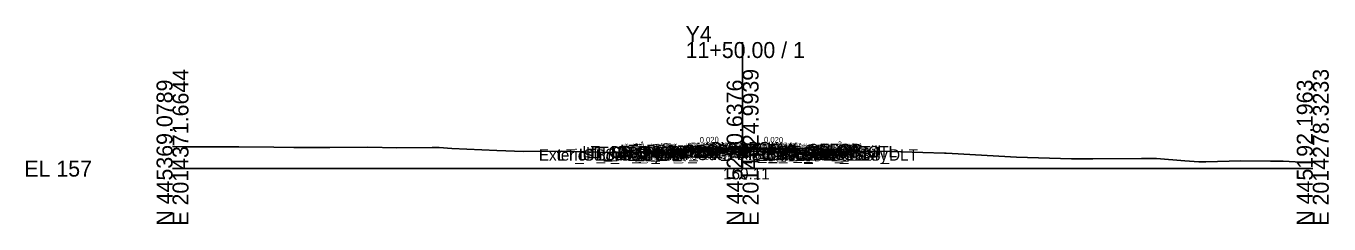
# Model space of a CAD drawing. Extents: x -26 to 203, y -10 to 4021.
# Drawn here: x -25.7 to 202.8, y 2990.3 to 3025 of the extents above; entities that cross this region are included whole.
import ezdxf

# ---------------------------------------------------------------- set-up
doc = ezdxf.new("R2010")
doc.units = 0
for name, color, linetype in [('Default', 7, 'Continuous'), ('Exist CMT Pavement', 7, 'Continuous'), ('Exist Cross Section Cell', 7, 'Continuous'), ('Exist XS Center Line Elevation Label', 7, 'Continuous'), ('Exist XS Ground Line', 7, 'Continuous'), ('Prop CMT Pvmt Course 1', 7, 'Continuous'), ('Prop CMT Pvmt Course 1 Wedge', 7, 'Continuous'), ('Prop CMT Pvmt Course 2', 7, 'Continuous'), ('Prop CMT Pvmt Course 2 Wedge', 7, 'Continuous'), ('Prop CMT Pvmt Course 3', 7, 'Continuous'), ('Prop CMT Pvmt Course 3 Wedge', 7, 'Continuous'), ('Prop CMT Pvmt Surface', 7, 'Continuous'), ('Prop CMT Pvmt Surface Shoulder', 7, 'Continuous'), ('Prop CMT Pvmt Wedge Surface 1', 7, 'Continuous'), ('Prop CMT Pvmt Wedge Surface 2', 7, 'Continuous'), ('Prop CMT Pvmt Wedge Surface 3', 7, 'Continuous'), ('Prop CMT Shld Paved Course 1', 7, 'Continuous'), ('Prop CMT Shld Paved Course 2', 7, 'Continuous'), ('Prop CMT Shld Paved Course 3', 7, 'Continuous'), ('Prop CMT Slope Grass', 7, 'Continuous'), ('Prop CMT Subgrade Earthwork', 7, 'Continuous'), ('Prop XS Earthwork Shape', 7, 'Continuous'), ('Prop XS SE Text', 7, 'Continuous'), ('Prop XS Side Slope Text', 7, 'Continuous'), ('Prop XS Wedging', 7, 'Continuous'), ('Scratch_Level_0', 7, 'Continuous')]:
    doc.layers.add(name, color=color, linetype=linetype)

msp = doc.modelspace()

# ---------------------------------------------------------------- linework, layer by layer
at = {"layer": 'Exist CMT Pavement'}
for points in [[(89.5, 3002.94), (99.49, 3003.12), (100, 3003.11)], [(100, 3003.11), (109.95, 3002.78)]]:
    msp.add_lwpolyline(points, dxfattribs=at)
at = {"layer": 'Exist Cross Section Cell'}
for p, q in [((100, 3000), (100, 3022.19)), ((0, 3000), (100, 3000)), ((100, 3000), (200, 3000))]:
    msp.add_line(p, q, dxfattribs=at)
at = {"layer": 'Exist XS Ground Line'}
msp.add_lwpolyline([(0, 3003.87), (0.32, 3003.86), (2.33, 3003.83), (6.15, 3003.82), (9.74, 3003.84), (11.63, 3003.83), (17.75, 3003.74), (21.27, 3003.7), (27.58, 3003.73), (34.24, 3003.79), (39.35, 3003.67), (45.55, 3003.68), (46.75, 3003.68), (49.01, 3003.54), (56.86, 3003.18), (61.55, 3003.01), (68.17, 3003.05), (69.67, 3003.03), (79.8, 3002.77), (85.7, 3002.84), (89.23, 3002.93), (97.46, 3003.08), (99.49, 3003.12), (100, 3003.11), (110.26, 3002.77), (111.13, 3002.79), (116.46, 3002.93), (120.92, 3003.06), (122.31, 3003.03), (124.01, 3003.04), (135.39, 3002.72), (135.72, 3002.7), (136.77, 3002.67), (148.04, 3002), (157.66, 3001.73), (161.4, 3001.73), (169.94, 3001.75), (172.58, 3001.77), (177.59, 3001.37), (179.99, 3001.19), (181.25, 3001.21), (187.39, 3001.36), (192.56, 3001.32), (194.79, 3001.3), (199.02, 3001.07), (200, 3001)], dxfattribs=at)
at = {"layer": 'Prop CMT Pvmt Course 1'}
for points in [[(100, 3003.67), (88.5, 3003.44)], [(88.5, 3003.44), (88.5, 3003.19)], [(88.5, 3003.19), (89.5, 3003.21)], [(89.5, 3003.33), (100, 3003.54)], [(89.5, 3003.21), (89.5, 3003.33)], [(100, 3003.42), (100, 3003.67)], [(100, 3003.67), (110.95, 3003.45)], [(100, 3003.42), (100, 3003.67)], [(100, 3003.54), (100, 3003.42), (100, 3003.42)], [(109.95, 3003.35), (100, 3003.54)], [(100, 3003.54), (100, 3003.42), (100, 3003.42)], [(109.95, 3003.22), (109.95, 3003.35)], [(110.95, 3003.2), (109.95, 3003.22)], [(110.95, 3003.45), (110.95, 3003.2)]]:
    msp.add_lwpolyline(points, dxfattribs=at)
at = {"layer": 'Prop CMT Pvmt Course 1 Wedge'}
for points in [[(100, 3003.54), (89.5, 3003.33)], [(100, 3003.54), (109.95, 3003.35)]]:
    msp.add_lwpolyline(points, dxfattribs=at)
at = {"layer": 'Prop CMT Pvmt Course 2'}
for points in [[(89.5, 3003.21), (88.5, 3003.19)], [(88.5, 3003.19), (88.5, 3002.86)], [(89.5, 3002.88), (89.5, 3003.21)], [(109.95, 3002.89), (109.95, 3003.22)], [(109.95, 3003.22), (110.95, 3003.2)], [(110.95, 3003.2), (110.95, 3002.87)], [(88.5, 3002.86), (89.5, 3002.88)], [(110.95, 3002.87), (109.95, 3002.89)]]:
    msp.add_lwpolyline(points, dxfattribs=at)
at = {"layer": 'Prop CMT Pvmt Course 2 Wedge'}
for points in [[(100, 3003.42), (89.5, 3003.21)], [(100, 3003.42), (109.95, 3003.22)]]:
    msp.add_lwpolyline(points, dxfattribs=at)
at = {"layer": 'Prop CMT Pvmt Course 3'}
for points in [[(89.5, 3002.88), (88.5, 3002.86)], [(88.5, 3002.86), (88.5, 3002.52)], [(88.5, 3002.52), (89.5, 3002.54)], [(89.5, 3002.54), (89.5, 3002.88)], [(109.95, 3002.89), (110.95, 3002.87)], [(109.95, 3002.55), (109.95, 3002.89)], [(110.95, 3002.53), (109.95, 3002.55)], [(110.95, 3002.87), (110.95, 3002.53)]]:
    msp.add_lwpolyline(points, dxfattribs=at)
at = {"layer": 'Prop CMT Pvmt Course 3 Wedge'}
for points in [[(100, 3003.09), (89.5, 3002.88)], [(100, 3003.09), (109.95, 3002.89)]]:
    msp.add_lwpolyline(points, dxfattribs=at)
at = {"layer": 'Prop CMT Pvmt Surface'}
for points in [[(100, 3003.67), (88.5, 3003.44)], [(100, 3003.67), (110.95, 3003.45)]]:
    msp.add_lwpolyline(points, dxfattribs=at)
at = {"layer": 'Prop CMT Pvmt Surface Shoulder'}
for points in [[(88.5, 3003.44), (88.5, 3003.44)], [(110.95, 3003.45), (110.95, 3003.45)]]:
    msp.add_lwpolyline(points, dxfattribs=at)
at = {"layer": 'Prop CMT Pvmt Wedge Surface 1'}
for points in [[(88.5, 3003.19), (88.5, 3003.44)], [(89.5, 3003.21), (88.5, 3003.19)], [(100, 3003.54), (89.5, 3003.33)], [(89.5, 3003.33), (89.5, 3003.21)], [(100, 3003.54), (109.95, 3003.35)], [(109.95, 3003.35), (109.95, 3003.22)], [(109.95, 3003.22), (110.95, 3003.2)], [(110.95, 3003.2), (110.95, 3003.45)]]:
    msp.add_lwpolyline(points, dxfattribs=at)
at = {"layer": 'Prop CMT Pvmt Wedge Surface 2'}
for points in [[(88.5, 3003.19), (88.5, 3003.44)], [(100, 3003.42), (88.5, 3003.19)], [(100, 3003.42), (110.95, 3003.2)], [(110.95, 3003.2), (110.95, 3003.45)]]:
    msp.add_lwpolyline(points, dxfattribs=at)
at = {"layer": 'Prop CMT Pvmt Wedge Surface 3'}
for points in [[(88.5, 3002.86), (88.5, 3003.44)], [(100, 3003.09), (88.5, 3002.86)], [(100, 3003.09), (110.95, 3002.87)], [(110.95, 3002.87), (110.95, 3003.45)]]:
    msp.add_lwpolyline(points, dxfattribs=at)
at = {"layer": 'Prop CMT Shld Paved Course 1'}
for points in [[(88.5, 3003.44), (88.24, 3003.18)], [(88.24, 3003.18), (88.5, 3003.19)], [(88.5, 3003.44), (88.5, 3003.44)], [(88.5, 3003.19), (88.5, 3003.44)], [(110.95, 3003.45), (110.95, 3003.45)], [(110.95, 3003.45), (111.2, 3003.2)], [(110.95, 3003.2), (110.95, 3003.45)], [(111.2, 3003.2), (110.95, 3003.2)]]:
    msp.add_lwpolyline(points, dxfattribs=at)
at = {"layer": 'Prop CMT Shld Paved Course 2'}
for points in [[(88.5, 3003.19), (88.24, 3003.18), (87.9, 3002.84)], [(88.5, 3002.86), (88.5, 3003.19)], [(110.95, 3003.2), (111.2, 3003.2), (111.54, 3002.86)], [(110.95, 3002.87), (110.95, 3003.2)], [(87.9, 3002.84), (88.5, 3002.86)], [(111.54, 3002.86), (110.95, 3002.87)]]:
    msp.add_lwpolyline(points, dxfattribs=at)
at = {"layer": 'Prop CMT Shld Paved Course 3'}
for points in [[(87.06, 3002.49), (88.5, 3002.52)], [(88.5, 3002.86), (87.9, 3002.84), (87.56, 3002.5)], [(88.5, 3002.52), (88.5, 3002.86)], [(110.95, 3002.87), (111.04, 3002.87), (111.54, 3002.86), (111.88, 3002.51)], [(110.95, 3002.53), (110.95, 3002.87)], [(112.38, 3002.5), (110.95, 3002.53)]]:
    msp.add_lwpolyline(points, dxfattribs=at)
at = {"layer": 'Prop CMT Slope Grass'}
for points in [[(88.5, 3003.44), (82.5, 3002.96), (82.01, 3002.8)], [(110.95, 3003.45), (116.95, 3002.97), (117.01, 3002.95)]]:
    msp.add_lwpolyline(points, dxfattribs=at)
at = {"layer": 'Prop CMT Subgrade Earthwork'}
for p, q in [((112.38, 3002.5), (117.01, 3002.95)), ((87.06, 3002.49), (82.01, 3002.8))]:
    msp.add_line(p, q, dxfattribs=at)
for points in [[(89.5, 3002.54), (89.5, 3002.94)], [(88.5, 3002.52), (87.06, 3002.49)], [(89.5, 3002.54), (88.5, 3002.52)], [(109.95, 3002.55), (109.95, 3002.78)], [(109.95, 3002.55), (110.95, 3002.53)], [(110.95, 3002.53), (112.38, 3002.5)]]:
    msp.add_lwpolyline(points, dxfattribs=at)
at = {"layer": 'Prop XS Earthwork Shape'}
for points in [[(85.7, 3002.84), (89.23, 3002.93), (89.5, 3002.94), (89.5, 3002.54), (88.5, 3002.52), (87.06, 3002.49), (82.01, 3002.8)], [(89.5, 3002.94), (97.46, 3003.08), (99.49, 3003.12)], [(110.95, 3002.53), (112.38, 3002.5), (117.01, 3002.95), (116.46, 3002.93), (111.13, 3002.79), (110.26, 3002.77), (109.95, 3002.78), (109.95, 3002.55)]]:
    msp.add_lwpolyline(points, close=True, dxfattribs=at)
at = {"layer": 'Prop XS Wedging'}
for p, q in [((100, 3003.54), (89.5, 3003.33)), ((89.5, 3003.21), (100, 3003.42)), ((100, 3003.42), (89.5, 3003.21)), ((89.5, 3003.33), (89.5, 3003.21)), ((89.5, 3003.21), (89.5, 3002.94)), ((89.5, 3002.94), (99.49, 3003.12)), ((99.49, 3003.12), (100, 3003.11)), ((109.95, 3003.35), (100, 3003.54)), ((100, 3003.54), (100, 3003.42)), ((100, 3003.42), (100, 3003.54)), ((100, 3003.42), (109.95, 3003.22)), ((109.95, 3003.22), (100, 3003.42)), ((100, 3003.11), (101.62, 3003.05)), ((101.62, 3003.05), (109.95, 3002.89)), ((109.95, 3002.89), (101.62, 3003.05)), ((101.62, 3003.05), (109.95, 3002.78)), ((109.95, 3003.22), (109.95, 3003.35)), ((109.95, 3002.89), (109.95, 3003.22)), ((109.95, 3002.78), (109.95, 3002.89))]:
    msp.add_line(p, q, dxfattribs=at)
for points in [[(89.5, 3002.94), (89.5, 3002.94)], [(109.95, 3002.78), (109.95, 3002.78)]]:
    msp.add_lwpolyline(points, dxfattribs=at)

# ---------------------------------------------------------------- texts
at = {"layer": 'Default'}
msp.add_text('-', height=0.0001, dxfattribs=at).set_placement((0, 3000))
at = {"layer": 'Exist Cross Section Cell'}
for s, p in [('Y4', (90, 3022.19)), ('11+50.00 / 1', (90, 3019.39)), ('EL 157', (-26, 2998.6))]:
    msp.add_text(s, height=2.8, dxfattribs=at).set_placement(p)
for s, p in [('E 2014371.6644', (2.8, 2990)), ('E 2014324.9939', (102.8, 2990)), ('E 2014278.3233', (202.8, 2990)), ('N 445369.0789', (0, 2990)), ('N 445280.6376', (100, 2990)), ('N 445192.1963', (200, 2990))]:
    msp.add_text(s, height=2.8, rotation=90, dxfattribs=at).set_placement(p)
at = {"layer": 'Exist XS Center Line Elevation Label'}
msp.add_text('160.11', height=2, dxfattribs=at).set_placement((96.56, 2998.11))
at = {"layer": 'Prop XS SE Text'}
for rotation, p in [(1.1458, (92.48, 3004.52)), (358.8542, (103.74, 3004.59))]:
    msp.add_text('0.020', height=1, rotation=rotation, dxfattribs=at).set_placement(p)
at = {"layer": 'Prop XS Side Slope Text'}
for rotation, p in [(18.4332, (81.26, 3003.34)), (341.5668, (116.47, 3003.92))]:
    msp.add_text('3:1', height=1, rotation=rotation, dxfattribs=at).set_placement(p)
at = {"layer": 'Scratch_Level_0'}
for s, p in [('Exterior Boundary', (64.25, 3001.4)), ('LT_Sub_OSS_DLT', (67.51, 3001.4)), ('LT_Sub_Trench_Out', (71.27, 3001.49)), ('LT_GS_OS_CTL', (71.87, 3001.96)), ('LT_Slope_Fill', (72.53, 3001.8)), ('LT_PS3_Shelf_Out', (73.38, 3001.83)), ('LT_Sub Tie Out', (76.84, 3001.94)), ('LT_PV_OEEOP_EG', (77.04, 3001.94)), ('LT_PS3_OEOP', (78.14, 3001.84)), ('LT_PS2_OEOP', (78.48, 3002.18)), ('LT_Sub_OEOT', (78.57, 3001.52)), ('LT_PV2_OEOT', (78.67, 3002.19)), ('LT_PV3_OEOT', (78.67, 3001.86)), ('LT_Sub_OEEOP', (78.71, 3001.54)), ('LT_PV2_OEEOP', (78.8, 3002.21)), ('LT_PV3_OEEOP', (78.8, 3001.88)), ('LT_PV1_OEOT', (79.24, 3002.44)), ('LT_PS1_OEOP', (79.3, 3002.44)), ('LT_PV1_OEEOP', (79.37, 3002.33)), ('RT_PV_IEEOP_EG', (88.14, 3002.11)), ('LT_PV_IEEOP_EG', (88.19, 3002.11)), ('RT_PV2_IEEOP', (89.91, 3002.42)), ('RT_PV3_IEEOP', (89.91, 3002.09)), ('LT_PV2_IEEOP', (89.95, 3002.42)), ('LT_PV3_IEEOP', (89.95, 3002.09)), ('RT_PV1_IEEOP', (90.47, 3002.54)), ('LT_PV1_IEEOP', (90.52, 3002.54)), ('PV2_PGL', (93.91, 3002.42)), ('PV1_PGL', (94.47, 3002.67)), ('RT_Sub_Trench_Out', (96.54, 3001.5)), ('RT_Sub Tie Out', (97.24, 3001.78)), ('RT_PV_OEEOP_EG', (97.44, 3001.78)), ('RT_PS3_Shelf_Out', (97.98, 3001.85)), ('RT_Sub_OEEOP', (99.11, 3001.55)), ('RT_PV2_OEEOP', (99.21, 3002.22)), ('RT_PV3_OEEOP', (99.21, 3001.89)), ('RT_PV1_OEEOP', (99.77, 3002.35)), ('RT_Sub_OEOT', (100.98, 3001.53)), ('RT_PV2_OEOT', (101.08, 3002.2)), ('RT_PV3_OEOT', (101.08, 3001.87)), ('RT_PS2_OEOP', (101.39, 3002.2)), ('RT_PV1_OEOT', (101.64, 3002.45)), ('RT_PS1_OEOP', (101.7, 3002.45)), ('RT_PS3_OEOP', (101.73, 3001.86)), ('Exterior Boundary', (104.03, 3001.4)), ('RT_GS_OS_CTL', (106.27, 3001.97)), ('RT_Slope_Cut', (106.6, 3001.95)), ('RT_Sub_OSS_DLT', (107.25, 3001.4)), ('RT_Slope_Fill', (107.49, 3001.95))]:
    msp.add_text(s, height=2, dxfattribs=at).set_placement(p)

doc.saveas('drawing.dxf')
